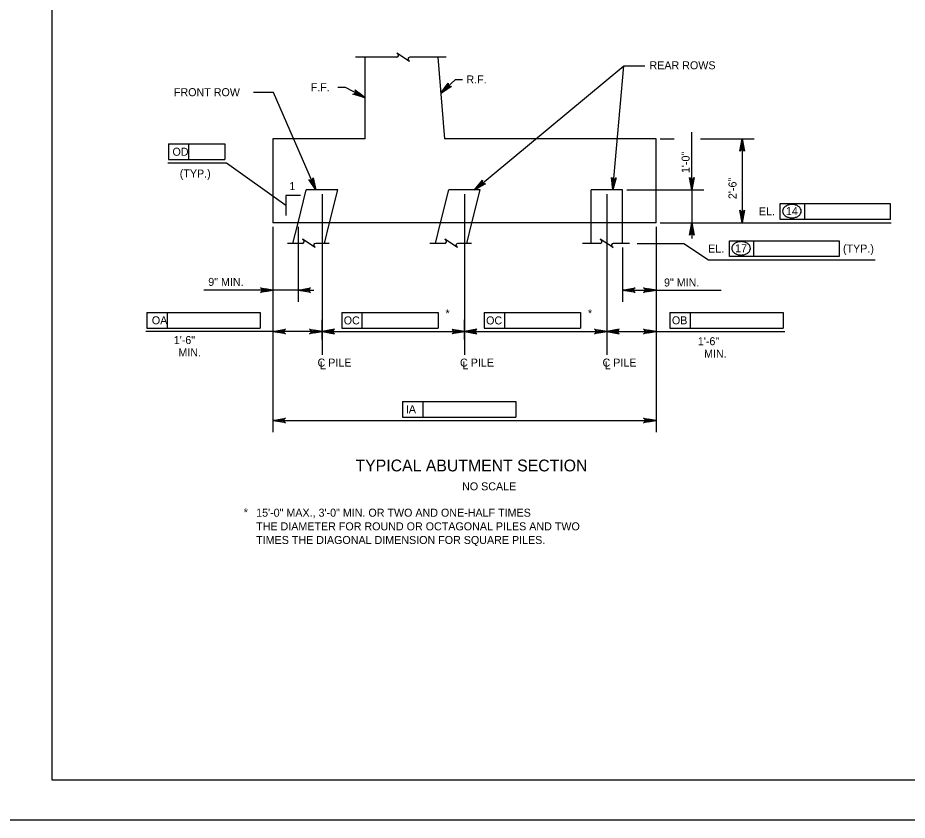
# Model space of a CAD drawing. Extents: x 638340 to 640242, y 295465 to 298435.
# Drawn here: x 639303.6 to 639636.8, y 295465.5 to 295766.2 of the extents above; entities that cross this region are included whole.
import ezdxf

# ---------------------------------------------------------------- set-up
doc = ezdxf.new("R2010")
doc.units = 0
for name, color, linetype in [('2', 7, 'Continuous'), ('4', 7, 'Continuous'), ('Level 2', 7, 'Continuous'), ('Level 4', 7, 'Continuous'), ('Level 5', 7, 'Continuous'), ('PLT-BNDY', 7, 'Continuous')]:
    doc.layers.add(name, color=color, linetype=linetype)

msp = doc.modelspace()

# ---------------------------------------------------------------- linework, layer by layer
at = {"layer": '2'}
for p, q in [((639316.46, 295480.46), (639316.46, 296044.46)), ((640102.46, 295480.46), (639316.46, 295480.46))]:
    msp.add_line(p, q, dxfattribs=at)
at = {"layer": 'Level 2'}
for p, q in [((639530.63, 295748.16), (639538.55, 295748.16)), ((639462.07, 295737.93), (639467.53, 295743.09)), ((639467.53, 295743.09), (639470.25, 295743.09)), ((639399.35, 295738.17), (639391.84, 295738.17)), ((639426.34, 295740.05), (639423.49, 295740.05)), ((639433.68, 295736.24), (639426.34, 295740.05)), ((639544.24, 295720.82), (639549.45, 295720.82)), ((639556.15, 295701.66), (639556.15, 295723.31)), ((639559.3, 295720.82), (639579.45, 295720.82)), ((639575.03, 295720.82), (639575.03, 295689.39)), ((639360.02, 295718.93), (639381.11, 295718.93)), ((639360.02, 295718.93), (639360.02, 295713.04)), ((639367.57, 295718.93), (639367.57, 295713.04)), ((639381.11, 295718.93), (639381.11, 295713.04)), ((639381.81, 295711.77), (639359.73, 295711.77)), ((639360.02, 295713.04), (639381.11, 295713.04)), ((639403.99, 295695.84), (639381.81, 295711.77)), ((639531.72, 295701.66), (639560.57, 295701.66)), ((639556.15, 295701.66), (639556.15, 295689.39)), ((639403.99, 295699.58), (639403.99, 295692.1)), ((639409.54, 295699.58), (639403.99, 295699.58)), ((639417.57, 295700.13), (639417.57, 295639.91)), ((639417.57, 295700.13), (639417.57, 295639.91)), ((639470.92, 295700.13), (639470.92, 295639.91)), ((639524.29, 295700.13), (639524.29, 295639.91)), ((639589.24, 295696.56), (639630.37, 295696.56)), ((639589.24, 295690.66), (639589.24, 295696.56)), ((639598.39, 295690.66), (639598.39, 295696.56)), ((639630.37, 295696.56), (639630.37, 295690.66)), ((639630.37, 295690.66), (639589.24, 295690.66)), ((639399.18, 295687.85), (639399.18, 295610.86)), ((639399.18, 295687.85), (639399.18, 295659.75)), ((639399.18, 295687.85), (639399.18, 295635.56)), ((639408.61, 295687.85), (639408.61, 295659.75)), ((639542.71, 295687.85), (639542.71, 295610.86)), ((639542.71, 295687.85), (639542.71, 295659.75)), ((639542.71, 295687.85), (639542.71, 295635.56)), ((639544.24, 295689.39), (639630.84, 295689.39)), ((639544.24, 295689.39), (639560.57, 295689.39)), ((639556.15, 295689.39), (639556.15, 295683.49)), ((639535.66, 295681.67), (639553.1, 295681.67)), ((639553.1, 295681.67), (639562.42, 295675.46)), ((639570.21, 295682.63), (639611.34, 295682.63)), ((639570.21, 295676.74), (639570.21, 295682.63)), ((639579.36, 295676.74), (639579.36, 295682.63)), ((639611.34, 295682.63), (639611.34, 295676.74)), ((639530.18, 295680.13), (639530.18, 295659.75)), ((639562.42, 295675.46), (639624.85, 295675.46)), ((639611.34, 295676.74), (639570.21, 295676.74)), ((639408.61, 295664.17), (639373.22, 295664.17)), ((639408.61, 295664.17), (639414.5, 295664.17)), ((639530.18, 295664.17), (639542.71, 295664.17)), ((639542.71, 295664.17), (639567.11, 295664.17)), ((639542.71, 295657.11), (639542.71, 295637.02)), ((639351.98, 295655.77), (639394.42, 295655.77)), ((639351.98, 295655.77), (639351.98, 295649.87)), ((639359.53, 295655.77), (639359.53, 295649.87)), ((639394.42, 295655.77), (639394.42, 295649.87)), ((639424.98, 295655.72), (639461.04, 295655.72)), ((639424.98, 295655.72), (639424.98, 295649.83)), ((639432.53, 295655.72), (639432.53, 295649.83)), ((639461.04, 295655.72), (639461.04, 295649.83)), ((639478.33, 295655.72), (639514.39, 295655.72)), ((639478.33, 295655.72), (639478.33, 295649.83)), ((639485.87, 295655.72), (639485.87, 295649.83)), ((639514.39, 295655.72), (639514.39, 295649.83)), ((639547.93, 295655.77), (639590.37, 295655.77)), ((639547.93, 295655.77), (639547.93, 295649.87)), ((639555.47, 295655.77), (639555.47, 295649.87)), ((639590.37, 295655.77), (639590.37, 295649.87)), ((639417.57, 295645.58), (639417.57, 295653.02)), ((639470.92, 295645.58), (639470.92, 295653.02)), ((639399.18, 295648.6), (639351.57, 295648.6)), ((639351.98, 295649.87), (639394.42, 295649.87)), ((639414.63, 295648.6), (639399.18, 295648.6)), ((639420.52, 295648.6), (639467.97, 295648.6)), ((639424.98, 295649.83), (639461.04, 295649.83)), ((639473.86, 295648.6), (639521.31, 295648.6)), ((639478.33, 295649.83), (639514.39, 295649.83)), ((639527.23, 295648.6), (639542.71, 295648.6)), ((639542.71, 295648.6), (639591.01, 295648.6)), ((639547.93, 295649.87), (639590.37, 295649.87)), ((639447.77, 295622.45), (639490.21, 295622.45)), ((639447.77, 295622.45), (639447.77, 295616.56)), ((639455.31, 295622.45), (639455.31, 295616.56)), ((639490.21, 295622.45), (639490.21, 295616.56)), ((639399.18, 295615.29), (639542.71, 295615.29)), ((639447.77, 295616.56), (639490.21, 295616.56))]:
    msp.add_line(p, q, dxfattribs=at)
for points in [[(639474.7, 295701.66), (639530.63, 295748.16)], [(639526.51, 295701.66), (639530.63, 295748.16)], [(639462.07, 295737.93), (639464.85, 295741.76), (639464.76, 295741.34), (639464.84, 295740.98), (639465.02, 295740.72), (639465.27, 295740.53), (639465.62, 295740.43), (639466.05, 295740.49), (639462.07, 295737.93), (639465.62, 295740.43), (639465.27, 295740.53), (639462.07, 295737.93), (639465.02, 295740.72), (639464.84, 295740.98), (639462.07, 295737.93), (639464.76, 295741.34)], [(639415.24, 295701.66), (639399.35, 295738.17)], [(639433.68, 295736.24), (639429.15, 295737.61), (639429.58, 295737.67), (639429.89, 295737.86), (639430.08, 295738.11), (639430.18, 295738.41), (639430.16, 295738.77), (639429.95, 295739.16), (639433.68, 295736.24), (639430.16, 295738.77), (639430.18, 295738.41), (639433.68, 295736.24), (639430.08, 295738.11), (639429.89, 295737.86), (639433.68, 295736.24), (639429.58, 295737.67)], [(639575.03, 295720.82), (639575.9, 295716.17), (639575.65, 295716.53), (639575.34, 295716.71), (639575.03, 295716.77), (639574.72, 295716.71), (639574.4, 295716.53), (639574.16, 295716.17), (639575.03, 295720.82), (639574.4, 295716.53), (639574.72, 295716.71), (639575.03, 295720.82), (639575.03, 295716.77), (639575.34, 295716.71), (639575.03, 295720.82), (639575.65, 295716.53)], [(639415.24, 295701.66), (639412.58, 295705.58), (639412.95, 295705.35), (639413.31, 295705.3), (639413.62, 295705.38), (639413.88, 295705.55), (639414.09, 295705.85), (639414.18, 295706.27), (639415.24, 295701.66), (639414.09, 295705.85), (639413.88, 295705.55), (639415.24, 295701.66), (639413.62, 295705.38), (639413.31, 295705.3), (639415.24, 295701.66), (639412.95, 295705.35)], [(639474.7, 295701.66), (639477.72, 295705.31), (639477.6, 295704.89), (639477.66, 295704.53), (639477.82, 295704.25), (639478.06, 295704.05), (639478.4, 295703.92), (639478.83, 295703.96), (639474.7, 295701.66), (639478.4, 295703.92), (639478.06, 295704.05), (639474.7, 295701.66), (639477.82, 295704.25), (639477.66, 295704.53), (639474.7, 295701.66), (639477.6, 295704.89)], [(639526.51, 295701.66), (639526.05, 295706.37), (639526.27, 295705.99), (639526.56, 295705.78), (639526.87, 295705.7), (639527.18, 295705.73), (639527.51, 295705.88), (639527.79, 295706.22), (639526.51, 295701.66), (639527.51, 295705.88), (639527.18, 295705.73), (639526.51, 295701.66), (639526.87, 295705.7), (639526.56, 295705.78), (639526.51, 295701.66), (639526.27, 295705.99)], [(639556.15, 295701.66), (639555.28, 295706.31), (639555.52, 295705.95), (639555.83, 295705.77), (639556.15, 295705.71), (639556.46, 295705.77), (639556.77, 295705.95), (639557.02, 295706.31), (639556.15, 295701.66), (639556.77, 295705.95), (639556.46, 295705.77), (639556.15, 295701.66), (639556.15, 295705.71), (639555.83, 295705.77), (639556.15, 295701.66), (639555.52, 295705.95)], [(639575.03, 295689.39), (639574.16, 295694.04), (639574.4, 295693.68), (639574.72, 295693.49), (639575.03, 295693.44), (639575.34, 295693.49), (639575.65, 295693.68), (639575.9, 295694.04), (639575.03, 295689.39), (639575.65, 295693.68), (639575.34, 295693.49), (639575.03, 295689.39), (639575.03, 295693.44), (639574.72, 295693.49), (639575.03, 295689.39), (639574.4, 295693.68)], [(639556.15, 295689.39), (639557.02, 295684.73), (639556.77, 295685.09), (639556.46, 295685.28), (639556.15, 295685.33), (639555.83, 295685.28), (639555.52, 295685.09), (639555.28, 295684.73), (639556.15, 295689.39), (639555.52, 295685.09), (639555.83, 295685.28), (639556.15, 295689.39), (639556.15, 295685.33), (639556.46, 295685.28), (639556.15, 295689.39), (639556.77, 295685.09)], [(639399.18, 295664.17), (639394.53, 295663.3), (639394.89, 295663.55), (639395.07, 295663.86), (639395.12, 295664.17), (639395.07, 295664.48), (639394.89, 295664.79), (639394.53, 295665.04), (639399.18, 295664.17), (639394.89, 295664.79), (639395.07, 295664.48), (639399.18, 295664.17), (639395.12, 295664.17), (639395.07, 295663.86), (639399.18, 295664.17), (639394.89, 295663.55)], [(639408.61, 295664.17), (639413.26, 295665.04), (639412.91, 295664.79), (639412.72, 295664.48), (639412.67, 295664.17), (639412.72, 295663.86), (639412.91, 295663.55), (639413.26, 295663.3), (639408.61, 295664.17), (639412.91, 295663.55), (639412.72, 295663.86), (639408.61, 295664.17), (639412.67, 295664.17), (639412.72, 295664.48), (639408.61, 295664.17), (639412.91, 295664.79)], [(639530.18, 295664.17), (639534.83, 295665.04), (639534.48, 295664.79), (639534.29, 295664.48), (639534.24, 295664.17), (639534.29, 295663.86), (639534.48, 295663.55), (639534.83, 295663.3), (639530.18, 295664.17), (639534.48, 295663.55), (639534.29, 295663.86), (639530.18, 295664.17), (639534.24, 295664.17), (639534.29, 295664.48), (639530.18, 295664.17), (639534.48, 295664.79)], [(639542.71, 295664.17), (639538.05, 295663.3), (639538.41, 295663.55), (639538.6, 295663.86), (639538.65, 295664.17), (639538.6, 295664.48), (639538.41, 295664.79), (639538.05, 295665.04), (639542.71, 295664.17), (639538.41, 295664.79), (639538.6, 295664.48), (639542.71, 295664.17), (639538.65, 295664.17), (639538.6, 295663.86), (639542.71, 295664.17), (639538.41, 295663.55)], [(639399.18, 295648.6), (639403.83, 295649.47), (639403.47, 295649.22), (639403.29, 295648.91), (639403.23, 295648.6), (639403.29, 295648.29), (639403.47, 295647.98), (639403.83, 295647.73), (639399.18, 295648.6), (639403.47, 295647.98), (639403.29, 295648.29), (639399.18, 295648.6), (639403.23, 295648.6), (639403.29, 295648.91), (639399.18, 295648.6), (639403.47, 295649.22)], [(639417.57, 295648.6), (639412.92, 295647.73), (639413.28, 295647.98), (639413.46, 295648.29), (639413.52, 295648.6), (639413.46, 295648.91), (639413.28, 295649.22), (639412.92, 295649.47), (639417.57, 295648.6), (639413.28, 295649.22), (639413.46, 295648.91), (639417.57, 295648.6), (639413.52, 295648.6), (639413.46, 295648.29), (639417.57, 295648.6), (639413.28, 295647.98)], [(639417.57, 295648.6), (639422.22, 295647.73), (639421.87, 295647.98), (639421.68, 295648.29), (639421.63, 295648.6), (639421.68, 295648.91), (639421.87, 295649.22), (639422.22, 295649.47), (639417.57, 295648.6), (639421.87, 295649.22), (639421.68, 295648.91), (639417.57, 295648.6), (639421.63, 295648.6), (639421.68, 295648.29), (639417.57, 295648.6), (639421.87, 295647.98)], [(639470.92, 295648.6), (639466.27, 295647.73), (639466.62, 295647.98), (639466.81, 295648.29), (639466.86, 295648.6), (639466.81, 295648.91), (639466.62, 295649.22), (639466.27, 295649.47), (639470.92, 295648.6), (639466.62, 295649.22), (639466.81, 295648.91), (639470.92, 295648.6), (639466.86, 295648.6), (639466.81, 295648.29), (639470.92, 295648.6), (639466.62, 295647.98)], [(639470.92, 295648.6), (639475.57, 295647.73), (639475.21, 295647.98), (639475.03, 295648.29), (639474.97, 295648.6), (639475.03, 295648.91), (639475.21, 295649.22), (639475.57, 295649.47), (639470.92, 295648.6), (639475.21, 295649.22), (639475.03, 295648.91), (639470.92, 295648.6), (639474.97, 295648.6), (639475.03, 295648.29), (639470.92, 295648.6), (639475.21, 295647.98)], [(639524.29, 295648.6), (639519.63, 295647.73), (639519.99, 295647.98), (639520.18, 295648.29), (639520.23, 295648.6), (639520.18, 295648.91), (639519.99, 295649.22), (639519.63, 295649.47), (639524.29, 295648.6), (639519.99, 295649.22), (639520.18, 295648.91), (639524.29, 295648.6), (639520.23, 295648.6), (639520.18, 295648.29), (639524.29, 295648.6), (639519.99, 295647.98)], [(639524.29, 295648.6), (639528.94, 295647.73), (639528.58, 295647.98), (639528.4, 295648.29), (639528.34, 295648.6), (639528.4, 295648.91), (639528.58, 295649.22), (639528.94, 295649.47), (639524.29, 295648.6), (639528.58, 295649.22), (639528.4, 295648.91), (639524.29, 295648.6), (639528.34, 295648.6), (639528.4, 295648.29), (639524.29, 295648.6), (639528.58, 295647.98)], [(639542.71, 295648.6), (639538.05, 295647.73), (639538.41, 295647.98), (639538.6, 295648.29), (639538.65, 295648.6), (639538.6, 295648.91), (639538.41, 295649.22), (639538.05, 295649.47), (639542.71, 295648.6), (639538.41, 295649.22), (639538.6, 295648.91), (639542.71, 295648.6), (639538.65, 295648.6), (639538.6, 295648.29), (639542.71, 295648.6), (639538.41, 295647.98)], [(639399.18, 295615.29), (639403.83, 295616.16), (639403.47, 295615.91), (639403.29, 295615.6), (639403.23, 295615.29), (639403.29, 295614.97), (639403.47, 295614.66), (639403.83, 295614.41), (639399.18, 295615.29), (639403.47, 295614.66), (639403.29, 295614.97), (639399.18, 295615.29), (639403.23, 295615.29), (639403.29, 295615.6), (639399.18, 295615.29), (639403.47, 295615.91)], [(639542.71, 295615.29), (639538.05, 295614.41), (639538.41, 295614.66), (639538.6, 295614.97), (639538.65, 295615.29), (639538.6, 295615.6), (639538.41, 295615.91), (639538.05, 295616.16), (639542.71, 295615.29), (639538.41, 295615.91), (639538.6, 295615.6), (639542.71, 295615.29), (639538.65, 295615.29), (639538.6, 295614.97), (639542.71, 295615.29), (639538.41, 295614.66)]]:
    msp.add_lwpolyline(points, dxfattribs=at)
for points in [[(639464.55, 295739.6), (639463.87, 295740.32), (639462.07, 295737.93)], [(639431.29, 295738.04), (639430.84, 295737.16), (639433.68, 295736.24)], [(639574.54, 295717.88), (639575.52, 295717.88), (639575.03, 295720.82)], [(639415.24, 295701.66), (639414.28, 295704.46), (639413.83, 295704.27)], [(639474.7, 295701.66), (639477.12, 295703.36), (639476.81, 295703.73)], [(639526.51, 295701.66), (639526.83, 295704.6), (639526.34, 295704.61)], [(639555.66, 295704.61), (639556.64, 295704.61), (639556.15, 295701.66)], [(639574.54, 295692.33), (639575.52, 295692.33), (639575.03, 295689.39)], [(639555.66, 295686.44), (639556.64, 295686.44), (639556.15, 295689.39)], [(639396.23, 295664.66), (639396.23, 295663.68), (639399.18, 295664.17)], [(639411.56, 295664.66), (639411.56, 295663.68), (639408.61, 295664.17)], [(639533.13, 295664.66), (639533.13, 295663.68), (639530.18, 295664.17)], [(639539.76, 295664.66), (639539.76, 295663.68), (639542.71, 295664.17)], [(639414.63, 295649.09), (639414.63, 295648.11), (639417.57, 295648.6)], [(639420.52, 295649.09), (639420.52, 295648.11), (639417.57, 295648.6)], [(639467.97, 295649.09), (639467.97, 295648.11), (639470.92, 295648.6)], [(639473.86, 295649.09), (639473.86, 295648.11), (639470.92, 295648.6)], [(639521.31, 295649.09), (639521.31, 295648.11), (639524.26, 295648.6)], [(639527.23, 295649.09), (639527.23, 295648.11), (639524.29, 295648.6)], [(639539.76, 295649.09), (639539.76, 295648.11), (639542.71, 295648.6)], [(639402.13, 295615.78), (639402.13, 295614.79), (639399.18, 295615.29)], [(639539.76, 295615.78), (639539.76, 295614.79), (639542.71, 295615.29)]]:
    msp.add_lwpolyline(points, close=True, dxfattribs=at)
for centre, radius, start, end in [((639591.94, 295693.72), 1.82, 149.9767, 180), ((639591.94, 295693.72), 1.82, 180, 210.0233), ((639592.74, 295693.25), 2.75, 125.6316, 149.9767), ((639593.27, 295692.52), 3.65, 106.5358, 125.6316), ((639593.61, 295691.36), 4.86, 90, 106.5358), ((639593.61, 295691.36), 4.86, 73.4642, 90), ((639593.95, 295692.52), 3.65, 54.3684, 73.4642), ((639594.48, 295693.25), 2.75, 30.0233, 54.3684), ((639595.28, 295693.72), 1.82, 0, 30.0233), ((639595.28, 295693.72), 1.82, 329.9767, 0), ((639592.74, 295694.18), 2.75, 210.0233, 234.3684), ((639593.27, 295694.92), 3.65, 234.3684, 253.4642), ((639593.61, 295696.08), 4.86, 253.4642, 270), ((639593.61, 295696.08), 4.86, 270, 286.5358), ((639593.95, 295694.92), 3.65, 286.5358, 305.6316), ((639594.48, 295694.18), 2.75, 305.6316, 329.9767), ((639572.9, 295679.79), 1.82, 149.9767, 180), ((639573.71, 295679.33), 2.75, 125.6316, 149.9767), ((639574.23, 295678.6), 3.65, 106.5358, 125.6316), ((639574.58, 295677.44), 4.86, 90, 106.5358), ((639574.58, 295677.44), 4.86, 73.4642, 90), ((639574.92, 295678.6), 3.65, 54.3684, 73.4642), ((639575.45, 295679.33), 2.75, 30.0233, 54.3684), ((639576.25, 295679.79), 1.82, 0, 30.0233), ((639572.9, 295679.79), 1.82, 180, 210.0233), ((639573.71, 295680.26), 2.75, 210.0233, 234.3684), ((639574.23, 295680.99), 3.65, 234.3684, 253.4642), ((639574.58, 295682.15), 4.86, 253.4642, 270), ((639574.58, 295682.15), 4.86, 270, 286.5358), ((639574.92, 295680.99), 3.65, 286.5358, 305.6316), ((639575.45, 295680.26), 2.75, 305.6316, 329.9767), ((639576.25, 295679.79), 1.82, 329.9767, 0)]:
    msp.add_arc(centre, radius, start, end, dxfattribs=at)
at = {"layer": 'Level 4'}
for p, q in [((639445.59, 295751.39), (639430.16, 295751.39)), ((639433.68, 295720.82), (639433.68, 295751.39)), ((639464.08, 295751.39), (639450.43, 295751.39)), ((639460.95, 295751.39), (639463.5, 295720.82)), ((639399.18, 295720.82), (639399.18, 295689.39)), ((639433.68, 295720.82), (639399.18, 295720.82)), ((639542.71, 295720.82), (639463.5, 295720.82)), ((639542.71, 295689.39), (639542.71, 295720.82)), ((639542.71, 295689.39), (639399.18, 295689.39))]:
    msp.add_line(p, q, dxfattribs=at)
msp.add_lwpolyline([(639450.08, 295750.07), (639450.38, 295749.88), (639445.58, 295752.9), (639445.9, 295752.7)], dxfattribs=at)
for centre, start, end in [((639445.52, 295752.1), 275.3286, 57.8672), ((639450.43, 295750.68), 90, 240)]:
    msp.add_arc(centre, 0.709, start, end, dxfattribs=at)
at = {"layer": 'Level 5'}
for p, q in [((639408.61, 295689.39), (639411.68, 295701.66)), ((639423.47, 295701.66), (639411.68, 295701.66)), ((639420.4, 295689.39), (639423.47, 295701.66)), ((639461.96, 295689.39), (639465.02, 295701.66)), ((639476.81, 295701.66), (639465.02, 295701.66)), ((639473.74, 295689.39), (639476.81, 295701.66)), ((639518.39, 295689.39), (639518.39, 295701.66)), ((639530.18, 295701.66), (639518.39, 295701.66)), ((639530.18, 295689.39), (639530.18, 295701.66)), ((639406.68, 295681.67), (639408.61, 295689.39)), ((639418.47, 295681.67), (639420.4, 295689.39)), ((639460.03, 295681.67), (639461.96, 295689.39)), ((639471.81, 295681.67), (639473.74, 295689.39)), ((639518.39, 295681.67), (639518.39, 295689.39)), ((639530.18, 295681.67), (639530.18, 295689.39)), ((639410.25, 295681.67), (639404.66, 295681.67)), ((639420.27, 295681.67), (639415.1, 295681.67)), ((639463.59, 295681.67), (639458, 295681.67)), ((639473.62, 295681.67), (639468.44, 295681.67)), ((639521.82, 295681.67), (639515.1, 295681.67)), ((639532.8, 295681.67), (639526.67, 295681.67))]:
    msp.add_line(p, q, dxfattribs=at)
for points in [[(639414.74, 295680.34), (639415.04, 295680.16), (639410.24, 295683.18), (639410.56, 295682.98)], [(639468.09, 295680.34), (639468.38, 295680.16), (639463.58, 295683.18), (639463.9, 295682.98)], [(639526.32, 295680.34), (639526.62, 295680.16), (639521.81, 295683.18), (639522.13, 295682.98)]]:
    msp.add_lwpolyline(points, dxfattribs=at)
for centre, start, end in [((639410.18, 295682.37), 275.3286, 57.8672), ((639415.1, 295680.96), 90, 240), ((639463.53, 295682.37), 275.3286, 57.8672), ((639468.44, 295680.96), 90, 240), ((639521.76, 295682.37), 275.3286, 57.8672), ((639526.67, 295680.96), 90, 240)]:
    msp.add_arc(centre, 0.709, start, end, dxfattribs=at)
at = {"layer": 'PLT-BNDY'}
msp.add_lwpolyline([(639276.46, 296059.46), (640117.46, 296059.46), (640117.46, 295465.46), (639276.46, 295465.46)], close=True, dxfattribs=at)

# ---------------------------------------------------------------- texts
at = {"layer": '2'}
msp.add_text('NO SCALE', height=3, dxfattribs=at).set_placement((639470.04, 295589.09))
at = {"layer": '4'}
msp.add_text('TYPICAL ABUTMENT SECTION', height=4.4294, dxfattribs=at).set_placement((639430.11, 295596.19))
at = {"layer": 'Level 2'}
for s, height, p in [('REAR ROWS', 3, (639540.25, 295746.9)), ('R.F.', 3, (639471.66, 295741.6)), ('F.F.', 3, (639413.33, 295738.69)), ('FRONT ROW', 3, (639362.07, 295736.82)), ('1', 3, (639405.32, 295701.62)), ('EL.', 3, (639581.24, 295692.15)), ('14', 3, (639591.37, 295692.26)), ('EL.', 3, (639562.21, 295678.22)), ('17', 3, (639572.32, 295678.33)), ('(TYP.)', 3, (639612.75, 295678.22)), ('9" MIN.', 3, (639374.93, 295665.72)), ('9" MIN.', 3, (639545.69, 295665.5)), ('1\'-6"', 3, (639362.01, 295643.92)), ('1\'-6"', 3, (639558.37, 295643.48)), ('MIN.', 3, (639363.75, 295639.27)), ('MIN.', 3, (639560.7, 295638.83)), ('C PILE', 3, (639415.89, 295635.47)), ('L', 3, (639416.77, 295634.45)), ('C PILE', 3, (639469.27, 295635.47)), ('L', 3, (639470.16, 295634.45)), ('C PILE', 3, (639522.66, 295635.47)), ('L', 3, (639523.54, 295634.45)), ('15\'-0" MAX., 3\'-0" MIN. OR TWO AND ONE-HALF TIMES', 3.0001, (639392.88, 295579.21)), ('THE DIAMETER FOR ROUND OR OCTAGONAL PILES AND TWO', 3.0001, (639392.88, 295574.1)), ('TIMES THE DIAGONAL DIMENSION FOR SQUARE PILES.', 3.0001, (639392.88, 295568.99))]:
    msp.add_text(s, height=height, dxfattribs=at).set_placement(p)
for s, rotation, p in [('OD', 359.9382, (639361.53, 295714.49)), ('1\'-0"', 90, (639555.28, 295708)), ('(TYP.)', 359.9382, (639364.26, 295706.35)), ('2\'-6"', 90, (639572.85, 295698.26)), ('*', 359.9382, (639463.82, 295653.95)), ('*', 359.9382, (639517.16, 295653.95)), ('OA', 359.9382, (639353.8, 295651.32)), ('OC', 359.9382, (639425.7, 295651.28)), ('OC', 359.9382, (639479.04, 295651.28)), ('OB', 359.9382, (639548.65, 295651.32)), ('IA', 359.9382, (639448.97, 295618.01)), ('*', 359.9382, (639388.23, 295579.37))]:
    msp.add_text(s, height=3, rotation=rotation, dxfattribs=at).set_placement(p)

doc.saveas('drawing.dxf')
